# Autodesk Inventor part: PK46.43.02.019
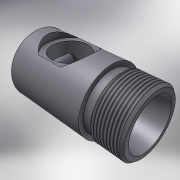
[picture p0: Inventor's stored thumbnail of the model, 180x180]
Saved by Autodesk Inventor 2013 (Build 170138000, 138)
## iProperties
Shininess: 64.0
Length Units: 11269
Angle Units: 11279
Time Units: 11290
Mass Units: 11283
Length Display Precision: 3
Angle Display Precision: 2
Created: 2002-03
Part Number: PK46.43.02.019
Material: Steel, Mild
Document SubType Name: Modeling
Designer: TEvgeniy
Density: 1 g/cm^3
Density: 0.0
Volumn: 0.0
Area: 0.0
PropertySet Name: Model Information
Control State: 0
Master: False
Checked Out: False
Checked Out Date: 2008-10-09
Last Check In Date: 2008-10-09
Author: TEvgeniy
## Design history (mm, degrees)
node "WorkPlane2"
node "WorkPlane1"
sketch "Sketch1"
  geometry: L1 (80, 19.4)-(80, 16.5); L2 (78.4, 21)-(80, 19.4); L3 (78.4, 21)-(61.5, 21); L4 (60, 19.5)-(61.5, 21); L5 (55, 19.5)-(60, 19.5); L6 (55, 22.5)-(55, 19.5); L7 (0, 22.5)-(55, 22.5); L8 through (0, 11.25) direction (0, -1); L9 through (3.892, 0) direction (1, 0); L10 (15, 12.5)-(7.783, 0); L11 (15, 12.5)-(61.181, 12.5); L12 (80, 16.5)-(61.181, 12.5); L13 through (3.892, 0) direction (1, 0)
  constraints: 23 end point, 7 horizontal, 4 vertical, 2 other
revolve "RevolutionAngle1" sketch "Sketch1" stored, may be unused: angle "d0" = 360 deg
sketch "Sketch2"
  geometry: L1 (0, -22.5)-(0, 22.5) reference; C1 r 16.5 at (25, 0)
  constraints: 1 centre point
  dimensions: "d2" = 33 diameter of C1; "d11" = 25 distance from line of L1 C1.centre
extrude "ExtrusionBlind1" cut sketch "Sketch2" distance "d3" = 5; taper "d4" = 0 deg
sketch "Sketch3"
  geometry: L1 (0, -22.5)-(0, 22.5) reference; C1 r 12.5 at (25, 0)
  constraints: 1 centre point
  dimensions: "d7" = 25 diameter of C1; "d10" = 25 distance from line of L1 C1.centre
extrude "ExtrusionBlind2" cut sketch "Sketch3" distance "d8" = 17.5; taper "d9" = 0 deg
thread "Thread1" dims "d12" = 10, "d13" = 0
body "Solid1"
other parameters: "d1" = 33 (derived), "d5" = 0, "d6" = 25 (derived)
